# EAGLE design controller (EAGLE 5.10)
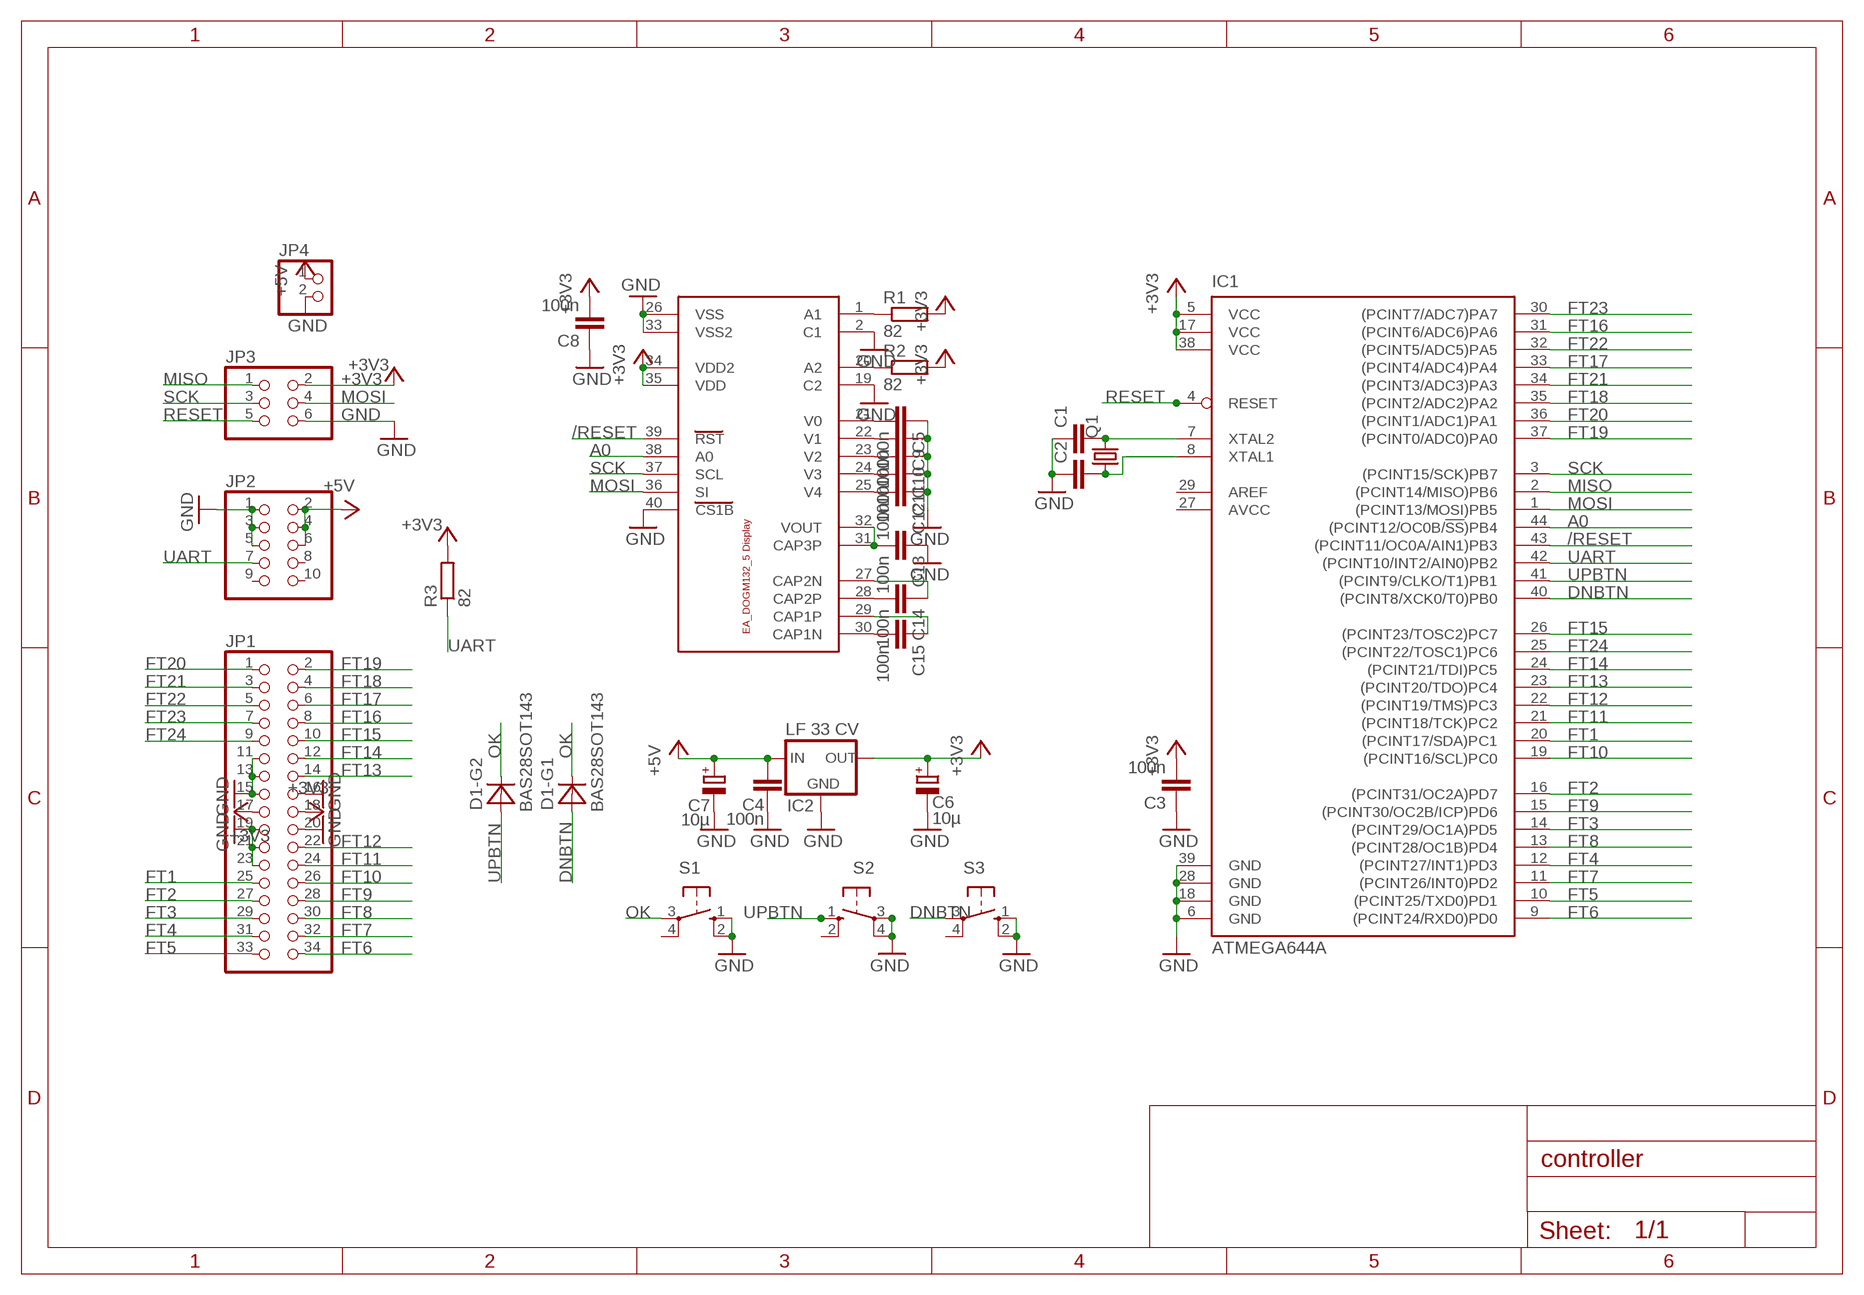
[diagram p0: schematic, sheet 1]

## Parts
C1  C-EUC1206  [C1206]
C2  C-EUC1206  [C1206]
C3  100n  C-EUC1206  [C1206]
C4  100n  C-EUC1206  [C1206]
C5  100n  C-EUC1206  [C1206]
C6  10µ  CPOL-EU153CLV-0505  [153CLV-0505]
C7  10µ  CPOL-EU153CLV-0505  [153CLV-0505]
C8  100n  C-EUC1206  [C1206]
C9  100n  C-EUC1206  [C1206]
C10  100n  C-EUC1206  [C1206]
C11  100n  C-EUC1206  [C1206]
C12  100n  C-EUC1206  [C1206]
C13  100n  C-EUC1206  [C1206]
C14  100n  C-EUC1206  [C1206]
C15  100n  C-EUC1206  [C1206]
D1  BAS28SOT143  [SOT143-R]
IC1  ATMEGA644A  [TQFP44]
IC2  LF 33 CV  78MXXS  [78MXXS]
JP1  PINHD-2X17  [2X17]
JP2  PINHD-2X5  [2X05]
JP3  PINHD-2X3  [2X03]
JP4  PINHD-1X2  [1X02]
Q1  CRYSTALHC49S  [HC49/S]
R1  82  R-EU_R1206  [R1206]
R2  82  R-EU_R1206  [R1206]
R3  82  R-EU_R1206  [R1206]
S1  10-XX  [B3F-10XX]
S2  10-XX  [B3F-10XX]
S3  10-XX  [B3F-10XX]
U$1  EA_DOG-M_DISPLAY  [E_DOG-M_DISPLAY]

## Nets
+3V3: C3.2 C6.+ C8.2 IC1.5(VCC) IC1.17(VCC) IC1.38(VCC) IC2.OUT JP1.17 JP1.18 JP3.2 R1.2 R2.2 R3.2 U$1.34(VDD2) U$1.35(VDD)
+5V: C4.2 C7.+ IC2.IN JP2.2 JP2.4 JP2.6 JP4.1
/RESET: IC1.43((PCINT11/OC0A/AIN1)PB3) U$1.39(RST)
A0: IC1.44((PCINT12/OC0B/!SS!)PB4) U$1.38(A0)
DNBTN: D1.4(-G1:A) IC1.40((PCINT8/XCK0/T0)PB0) S3.3(P)
FT1: IC1.20((PCINT17/SDA)PC1) JP1.25
FT2: IC1.16((PCINT31/OC2A)PD7) JP1.27
FT3: IC1.14((PCINT29/OC1A)PD5) JP1.29
FT4: IC1.12((PCINT27/INT1)PD3) JP1.31
FT5: IC1.10((PCINT25/TXD0)PD1) JP1.33
FT6: IC1.9((PCINT24/RXD0)PD0) JP1.34
FT7: IC1.11((PCINT26/INT0)PD2) JP1.32
FT8: IC1.13((PCINT28/OC1B)PD4) JP1.30
FT9: IC1.15((PCINT30/OC2B/ICP)PD6) JP1.28
FT10: IC1.19((PCINT16/SCL)PC0) JP1.26
FT11: IC1.21((PCINT18/TCK)PC2) JP1.24
FT12: IC1.22((PCINT19/TMS)PC3) JP1.22
FT13: IC1.23((PCINT20/TDO)PC4) JP1.14
FT14: IC1.24((PCINT21/TDI)PC5) JP1.12
FT15: IC1.26((PCINT23/TOSC2)PC7) JP1.10
FT16: IC1.31((PCINT6/ADC6)PA6) JP1.8
FT17: IC1.33((PCINT4/ADC4)PA4) JP1.6
FT18: IC1.35((PCINT2/ADC2)PA2) JP1.4
FT19: IC1.37((PCINT0/ADC0)PA0) JP1.2
FT20: IC1.36((PCINT1/ADC1)PA1) JP1.1
FT21: IC1.34((PCINT3/ADC3)PA3) JP1.3
FT22: IC1.32((PCINT5/ADC5)PA5) JP1.5
FT23: IC1.30((PCINT7/ADC7)PA7) JP1.7
FT24: IC1.25((PCINT22/TOSC1)PC6) JP1.9
GND: C1.1 C2.1 C3.1 C4.1 C5.1 C6.- C7.- C8.1 C9.1 C10.1 C11.1 C12.1 C13.1 IC1.6(GND) IC1.18(GND) IC1.28(GND) IC1.39(GND) IC2.GND JP1.11 JP1.13 JP1.15 JP1.16 JP1.19 JP1.20 JP1.21 JP1.23 JP2.1 JP2.3 JP2.5 JP3.6 JP4.2 S1.1(S) S1.2(S1) S2.3(P) S2.4(P1) S3.1(S) S3.2(S1) U$1.2(C1) U$1.19(C2) U$1.26(VSS) U$1.33(VSS2) U$1.40(CS1B)
MISO: IC1.2((PCINT14/MISO)PB6) JP3.1
MOSI: IC1.1((PCINT13/MOSI)PB5) JP3.4 U$1.36(SI)
N$1: C1.2 IC1.7(XTAL2) Q1.2
N$2: C2.2 IC1.8(XTAL1) Q1.1
N$3: C5.2 U$1.21(V0)
N$4: C9.2 U$1.22(V1)
N$5: C10.2 U$1.23(V2)
N$6: C11.2 U$1.24(V3)
N$7: C12.2 U$1.25(V4)
N$8: C14.2 U$1.28(CAP2P)
N$9: C15.2 U$1.30(CAP1N)
N$10: C13.2 U$1.31(CAP3P) U$1.32(VOUT)
N$11: R1.1 U$1.1(A1)
N$12: R2.1 U$1.20(A2)
N$15: C14.1 U$1.27(CAP2N)
N$16: C15.1 U$1.29(CAP1P)
OK: D1.1(-G1:C) D1.2(-G2:C) S1.3(P)
RESET: IC1.4(RESET) JP3.5
SCK: IC1.3((PCINT15/SCK)PB7) JP3.3 U$1.37(SCL)
UART: IC1.42((PCINT10/INT2/AIN0)PB2) JP2.7 R3.1
UPBTN: D1.3(-G2:A) IC1.41((PCINT9/CLKO/T1)PB1) S2.1(S)
Unconnected: IC1.29(AREF) JP2.8 JP2.9 JP2.10 S1.4(P1) S2.2(S1) S3.4(P1)

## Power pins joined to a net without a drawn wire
AVCC: IC1.27(AVCC)

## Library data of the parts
C1-C5 C8-C15 = rcl:C-EU: CAPACITOR, European symbol
C6 C7 = rcl:CPOL-EU: POLARIZED CAPACITOR, European symbol
D1 = diode:BAS28: The BAS28 consists of two high-speed switching diodes, fabricated in planar technology, and encapsulated in the small plastic SMD SOT143 package. The diodes are not connected.
IC1 = atmel:ATMEGA644: 8-bit Microcontroller with 64K Bytes In-System Programmable Flash Source: http://www.atmel.com/dyn/resources/prod_documents/doc2593.pdf
IC2 = v-reg:78MXXS: VOLTAGE REGULATOR
JP1 = pinhead:PINHD-2X17: PIN HEADER
JP2 = pinhead:PINHD-2X5: PIN HEADER
JP3 = pinhead:PINHD-2X3: PIN HEADER
JP4 = pinhead:PINHD-1X2: PIN HEADER
Q1 = crystal:CRYSTAL: CRYSTAL
R1-R3 = rcl:R-EU_: RESISTOR, European symbol
S1-S3 = switch-omron:10-XX: OMRON SWITCH
U$1 = display_ea_dogm132:EA_DOG-M_DISPLAY

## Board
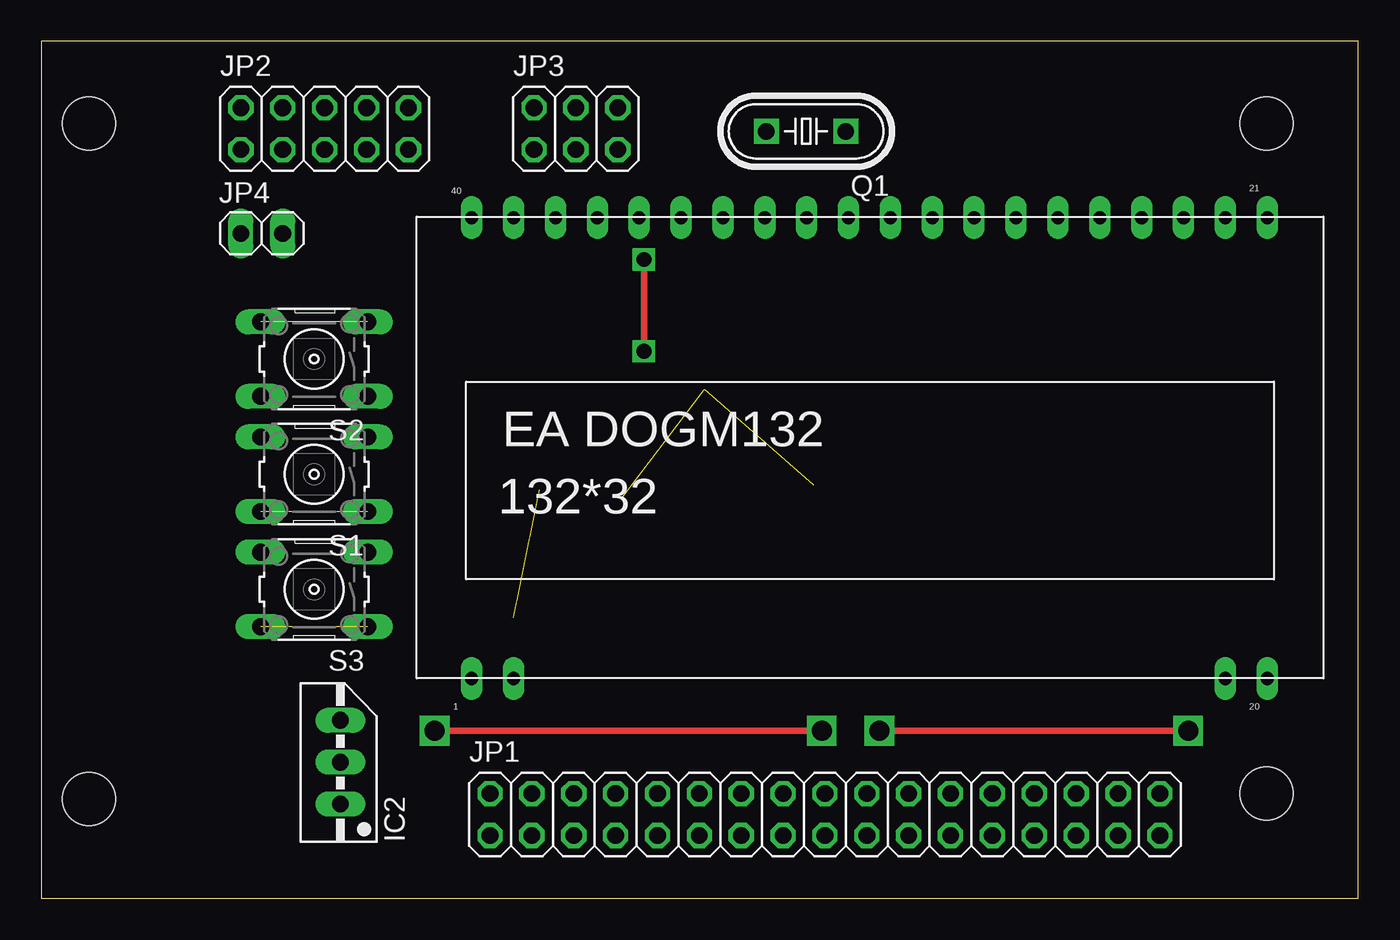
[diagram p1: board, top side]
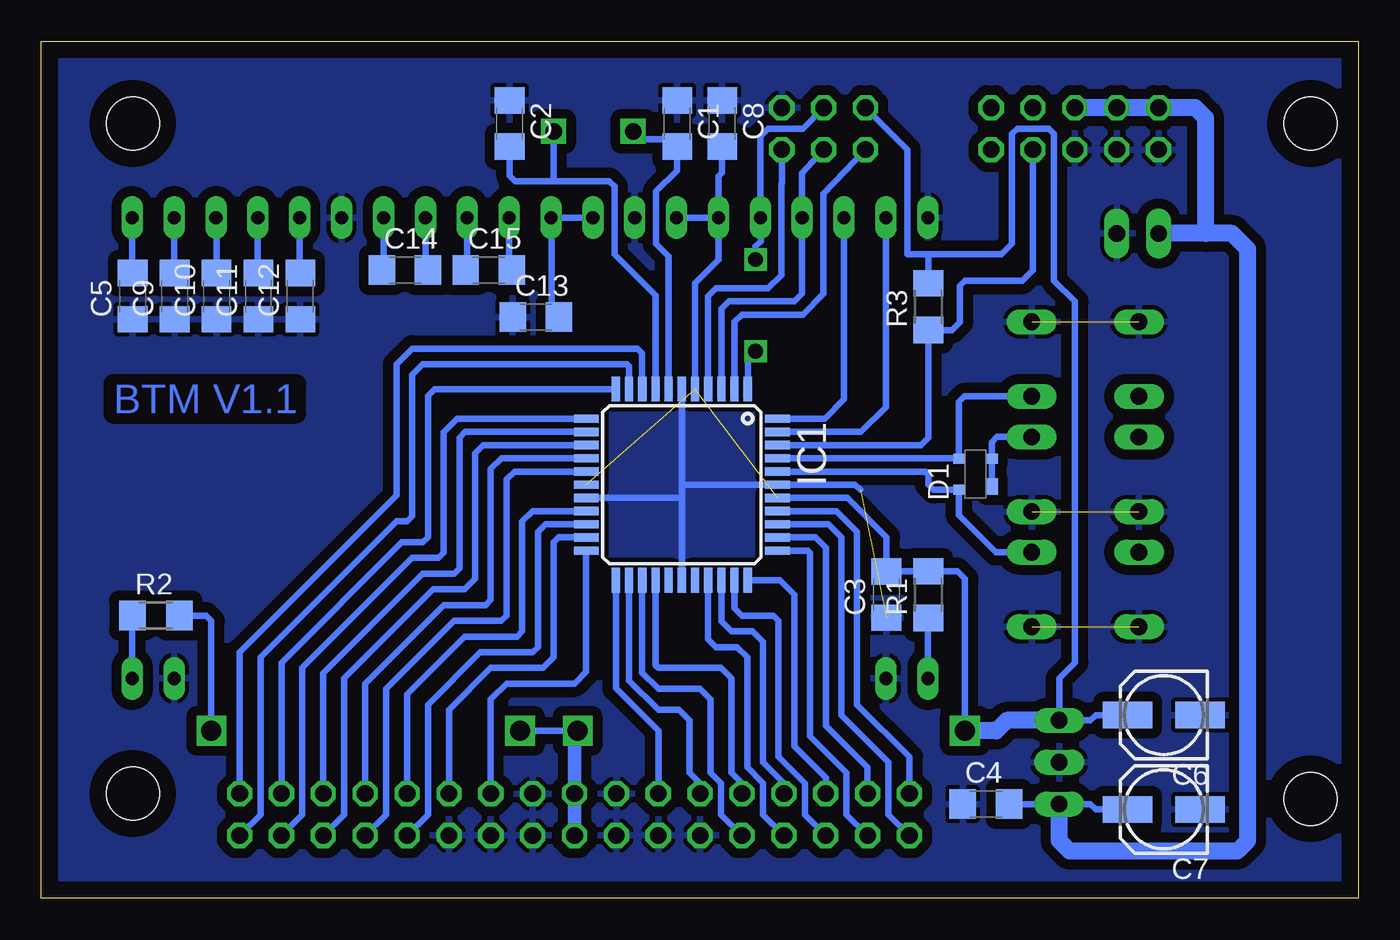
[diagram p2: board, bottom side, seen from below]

Size 79.9 x 51.98 mm. Coordinates in mm from the lower left corner, seen from the top.
Outline: 0,0 79.9,0 79.9,51.98 0,51.98 0,0
Copper layers (1*16): Top 0.035mm / dielectric 1.5mm / Bottom 0.035mm
Design rules "default": minimum track width 10mil, minimum drill 24mil, track to track 8mil, track to pad 8mil, pad to pad 8mil, via to via 8mil, smd to smd 8mil, copper to edge 40mil, drill to drill 8mil, minimum pad ring 10mil, minimum via ring 8mil, stop-mask expansion 4mil, vias tented up to drill 0mil, thermal gap 10mil
Holes 3.2 mm at 74.34,46.99 74.34,6.35 2.9,46.99 2.9,6.03

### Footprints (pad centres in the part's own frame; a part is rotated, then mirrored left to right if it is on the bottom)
C1206 = smd 1.6 x 1.8: 1 -1.4,0; 2 1.4,0
153CLV-0505 = smd 3 x 1.6: + 2.2,0; - -2.2,0
SOT143-R = smd 1 x 0.7: 1 -0.75,-1 | smd 0.6 x 0.7: 2 0.95,-1; 3 0.95,1; 4 -0.95,1
TQFP44 = smd 1.5 x 0.5: 1 -5.8,4; 2 -5.8,3.2; 3 -5.8,2.4; 4 -5.8,1.6; 5 -5.8,0.8; 6 -5.8,0; 7 -5.8,-0.8; 8 -5.8,-1.6; 9 -5.8,-2.4; 10 -5.8,-3.2; 11 -5.8,-4; 23 5.8,-4; 24 5.8,-3.2; 25 5.8,-2.4; 26 5.8,-1.6; 27 5.8,-0.8; 28 5.8,0; 29 5.8,0.8; 30 5.8,1.6; 31 5.8,2.4; 32 5.8,3.2; 33 5.8,4 | smd 0.5 x 1.5: 12 -4,-5.8; 13 -3.2,-5.8; 14 -2.4,-5.8; 15 -1.6,-5.8; 16 -0.8,-5.8; 17 0,-5.8; 18 0.8,-5.8; 19 1.6,-5.8; 20 2.4,-5.8; 21 3.2,-5.8; 22 4,-5.8; 34 4,5.8; 35 3.2,5.8; 36 2.4,5.8; 37 1.6,5.8; 38 0.8,5.8; 39 0,5.8; 40 -0.8,5.8; 41 -1.6,5.8; 42 -2.4,5.8; 43 -3.2,5.8; 44 -4,5.8
78MXXS = drill 1.016 long: GND 0,-2.54; IN -2.54,-2.54; OUT 2.54,-2.54
2X17 = drill 1.016 octagon: 1 -20.32,-1.27; 2 -20.32,1.27; 3 -17.78,-1.27; 4 -17.78,1.27; 5 -15.24,-1.27; 6 -15.24,1.27; 7 -12.7,-1.27; 8 -12.7,1.27; 9 -10.16,-1.27; 10 -10.16,1.27; 11 -7.62,-1.27; 12 -7.62,1.27; 13 -5.08,-1.27; 14 -5.08,1.27; 15 -2.54,-1.27; 16 -2.54,1.27; 17 0,-1.27; 18 0,1.27; 19 2.54,-1.27; 20 2.54,1.27; 21 5.08,-1.27; 22 5.08,1.27; 23 7.62,-1.27; 24 7.62,1.27; 25 10.16,-1.27; 26 10.16,1.27; 27 12.7,-1.27; 28 12.7,1.27; 29 15.24,-1.27; 30 15.24,1.27; 31 17.78,-1.27; 32 17.78,1.27; 33 20.32,-1.27; 34 20.32,1.27
2X05 = drill 1.016 octagon: 1 -5.08,-1.27; 2 -5.08,1.27; 3 -2.54,-1.27; 4 -2.54,1.27; 5 0,-1.27; 6 0,1.27; 7 2.54,-1.27; 8 2.54,1.27; 9 5.08,-1.27; 10 5.08,1.27
2X03 = drill 1.016 octagon: 1 -2.54,-1.27; 2 -2.54,1.27; 3 0,-1.27; 4 0,1.27; 5 2.54,-1.27; 6 2.54,1.27
1X02 = drill 1.016 long: 1 -1.27,0; 2 1.27,0
HC49/S = drill 1 square: 1 -2.413,0; 2 2.413,0
R1206 = smd 1.6 x 1.803: 1 -1.422,0; 2 1.422,0
B3F-10XX = drill 1.016 long: 1 -3.251,2.261; 2 3.251,2.261; 3 -3.251,-2.261; 4 3.251,-2.261
E_DOG-M_DISPLAY = drill 0.8 long: 1 3.334,0; 2 5.874,0; 19 49.054,0; 20 51.594,0; 21 51.594,27.94; 22 49.054,27.94; 23 46.514,27.94; 24 43.974,27.94; 25 41.434,27.94; 26 38.894,27.94; 27 36.354,27.94; 28 33.814,27.94; 29 31.274,27.94; 30 28.734,27.94; 31 26.194,27.94; 32 23.654,27.94; 33 21.114,27.94; 34 18.574,27.94; 35 16.034,27.94; 36 13.494,27.94; 37 10.954,27.94; 38 8.414,27.94; 39 5.874,27.94; 40 3.334,27.94

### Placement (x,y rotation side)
C1  41.32,46.99 270 bottom
C2  51.48,46.99 270 bottom
C3  28.62,18.41 90 bottom
C4  22.59,5.71 0 bottom
C5  74.34,36.51 90 bottom
C6  11.79,11.11 180 bottom
C7  11.79,5.4 180 bottom
C8  38.59,46.99 270 bottom
C9  71.8,36.51 90 bottom
C10  69.26,36.51 90 bottom
C11  66.72,36.51 90 bottom
C12  64.18,36.51 90 bottom
C13  49.89,35.24 0 bottom
C14  57.83,38.1 0 bottom
C15  52.75,38.1 0 bottom
D1  23.22,25.72 90 bottom
IC1  41.04,25.08 270 bottom
IC2  15.6,8.26 90 top
JP1  47.55,5.08 0 top
JP2  17.19,46.67 0 top
JP3  32.43,46.67 0 top
JP4  13.38,40.32 0 top
Q1  46.4,46.51 180 top
R1  26.08,18.41 90 bottom
R2  72.94,17.14 0 bottom
R3  26.08,35.88 90 bottom
S1  16.56,25.72 180 top
S2  16.56,32.7 180 top
S3  16.56,18.73 180 top
U$1  22.78,13.34 0 top

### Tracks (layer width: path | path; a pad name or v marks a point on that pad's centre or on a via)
+3V3  (via drill 1.2)  (2 unrouted)
  Top 0.406: v50.85,10.16 v69.58,10.16 | v23.86,10.16 v47.35,10.16
  Bottom 0.406: IC1.5 40.24,37.31 38.81,38.73 U$1.35 | U$1.35 U$1.34 | U$1.35 38.81,43.78 38.59,44.01 C8.2 | IC1.38 31,24.28 28.62,21.91 C3.2 28.6,19.84 R1.2 24.33,19.84 23.86,19.37 v23.86,10.16 | R2.2 69.9,17.14 69.58,16.83 v69.58,10.16 | v47.35,10.16 v50.85,10.16 | C6.+ 15.92,11.11 16.24,10.79 IC2.OUT 18.15,13.34 17.19,14.29 17.19,36.2 18.46,37.47 18.46,46.35 18.78,46.67 20.68,46.67 21,46.35 21,39.69 21.64,39.05 26.08,39.05 | JP3.2 27.35,45.4 27.35,39.05 26.08,39.05 | 26.08,39.05 R3.2
  Bottom 0.813: JP1.17 JP1.18 47.55,9.97 v47.35,10.16
  Bottom 1.016: v23.86,10.16 21.95,10.16 21.32,10.79 IC2.OUT
+5V
  Bottom 0.406: C4.2 IC2.IN 16.24,5.71 15.92,5.4 C7.+
  Bottom 1.016: JP2.6 JP2.4 JP2.2 9.89,47.94 9.25,47.31 9.25,40.32 | IC2.IN 18.15,3.49 17.51,2.86 7.35,2.86 6.72,3.49 6.72,39.37 7.67,40.32 9.25,40.32 | 9.25,40.32 JP4.1
/RESET
  Bottom 0.406: IC1.43 30.16,28.28 28.65,29.79 U$1.39
A0
  Bottom 0.406: U$1.38 31.19,30.25 32.36,29.08 IC1.44
DNBTN
  Bottom 0.406: IC1.40 26.25,25.88 26.08,25.72 26.08,25.08 25.77,24.77 D1.4 24.22,23.23 21.99,20.99 S3.3
FT1
  Bottom 0.406: IC1.20 49.31,22.68 49.77,22.23 49.77,15.24 50.09,14.92 53.26,14.92 56.44,11.75 56.44,5.08 JP1.25
FT2
  Bottom 0.406: IC1.16 51.19,25.88 51.67,25.4 51.67,17.14 51.99,16.83 54.85,16.83 58.98,12.7 58.98,5.08 JP1.27
FT3
  Bottom 0.406: IC1.14 53.08,27.48 53.58,26.99 53.58,19.37 54.21,18.73 56.12,18.73 61.52,13.34 61.52,5.08 JP1.29
FT4
  Bottom 0.406: IC1.12 54.66,29.08 55.48,28.26 55.48,20.95 55.8,20.64 57.39,20.64 64.05,13.97 64.05,5.08 JP1.31
FT5
  Bottom 0.406: IC1.10 44.24,32.25 44.37,32.38 56.75,32.38 57.39,31.75 57.39,23.18 57.7,22.86 58.34,22.86 66.59,14.61 66.59,5.08 JP1.33
FT6
  Bottom 0.406: IC1.9 43.44,33.04 43.74,33.34 57.39,33.34 58.34,32.38 58.34,24.45 67.86,14.92 JP1.34
FT7
  Bottom 0.406: IC1.11 56.03,30.88 56.44,30.48 56.44,21.91 56.75,21.59 58.02,21.59 65.33,14.29 JP1.32
FT8
  Bottom 0.406: IC1.13 54.19,28.28 54.53,27.94 54.53,20 54.85,19.68 56.75,19.68 62.78,13.65 JP1.30
FT9
  Bottom 0.406: IC1.15 51.98,26.68 52.63,26.04 52.63,18.1 52.94,17.78 55.48,17.78 60.24,13.02 JP1.28
FT10
  Bottom 0.406: IC1.19 50.1,23.48 50.72,22.86 50.72,16.19 51.04,15.88 54.21,15.88 57.7,12.38 JP1.26
FT11
  Bottom 0.406: IC1.21 48.52,21.88 48.81,21.59 48.81,14.61 49.45,13.97 52.63,13.97 55.16,11.43 JP1.24
FT12
  Bottom 0.406: IC1.22 46.84,13.73 47.55,13.02 51.67,13.02 52.63,12.06 JP1.22
FT13
  Bottom 0.406: IC1.23 45.04,12.73 42.46,10.16 JP1.14
FT14
  Bottom 0.406: JP1.12 39.92,6.99 40.56,7.62 40.56,10.79 41.2,11.43 42.46,11.43 44.24,13.2 IC1.24
FT15
  Bottom 0.406: JP1.10 37.38,6.99 38.02,7.62 38.02,13.34 38.66,13.97 42.46,13.97 42.64,14.14 IC1.26
FT16
  Bottom 0.406: JP1.8 34.84,6.99 36.12,8.26 36.12,15.56 36.75,16.19 38.02,16.19 38.64,16.81 IC1.31
FT17
  Bottom 0.406: JP1.6 32.31,7.3 34.21,9.21 34.21,18.41 35.08,19.28 IC1.33
FT18
  Bottom 0.406: JP1.4 29.77,7.94 32.31,10.48 32.31,21.27 32.91,21.88 IC1.35
FT19
  Bottom 0.406: IC1.37 31.66,23.48 30.4,22.23 30.4,11.75 27.22,8.57 JP1.2
FT20
  Bottom 0.406: JP1.1 28.5,5.08 28.5,8.26 31.35,11.11 31.35,21.91 32.13,22.68 IC1.36
FT21
  Bottom 0.406: IC1.34 33.38,21.08 33.26,20.95 33.26,9.84 31.04,7.62 31.04,5.08 JP1.3
FT22
  Bottom 0.406: JP1.5 33.58,5.08 33.58,6.99 35.16,8.57 35.16,16.83 35.48,17.14 37.38,17.14 37.84,17.6 IC1.32
FT23
  Bottom 0.406: JP1.7 36.12,5.08 36.12,6.99 37.07,7.94 37.07,14.61 37.7,15.24 38.97,15.24 39.44,15.7 IC1.30
FT24
  Bottom 0.406: JP1.9 38.66,5.08 38.66,6.99 39.29,7.62 39.29,12.06 39.92,12.7 42.46,12.7 43.44,13.67 IC1.25
GND  (4 unrouted)
  Bottom 0.406: 41.04,24.28 IC1.28 | 41.04,24.28 IC1.18 | 41.04,24.92 41.04,24.28 | 41.04,24.92 IC1.6 | 41.04,24.92 40.88,25.08 IC1.39 30.53,25.08 30.21,24.77
  pour Bottom: 36.99,29.05 36.99,21.11 44.93,21.11 44.93,29.05
  pour Bottom (isolate 0.61): 0,0 79.9,0 79.9,51.98 0,51.98
MISO
  Bottom 0.406: IC1.2 37.84,34.95 37.38,35.4 33.7,35.4 32.43,36.67 32.43,42.73 JP3.1
MOSI  (via drill 0.9)
  Top 0.406: v36.56,33.18 v36.56,38.73
  Bottom 0.406: IC1.1 37.04,32.7 v36.56,33.18 | v36.56,38.73 36.56,39.53 36.24,39.85 36.24,41.24 U$1.36 36.27,46.22 35.81,46.68 33.69,46.68 JP3.4
N$1
  Bottom 0.406: IC1.7 41.84,38.93 42.59,39.69 42.59,42.86 41.32,44.13 C1.2 41.32,46.04 43.86,46.04 43.99,46.16 Q1.2
N$2
  Bottom 0.406: IC1.8 42.64,36.56 45.13,39.05 45.13,43.18 45.45,43.5 48.94,43.5 | 48.94,43.5 51.16,43.5 51.48,43.81 C2.2 | Q1.1 48.82,43.62 48.94,43.5
N$3
  Bottom 0.406: C5.2 74.37,37.94 U$1.21
N$4
  Bottom 0.406: C9.2 71.83,37.94 U$1.22
N$5
  Bottom 0.406: U$1.23 69.26,41.24 C10.2
N$6
  Bottom 0.406: C11.2 66.75,37.94 U$1.24
N$7
  Bottom 0.406: C12.2 64.21,37.94 U$1.25
N$8
  Bottom 0.406: C14.2 56.59,38.26 U$1.28
N$9
  Bottom 0.406: C15.2 51.51,38.26 U$1.30
N$10
  Bottom 0.406: 46.42,41.27 U$1.32 U$1.31 48.94,41.24 48.94,35.69 C13.2
N$11
  Bottom 0.406: U$1.1 26.11,16.96 R1.1
N$12
  Bottom 0.406: R2.1 74.37,15.88 U$1.20
N$15
  Bottom 0.406: C14.1 59.13,38.2 U$1.27
N$16
  Bottom 0.406: C15.1 54.05,38.2 U$1.29
OK
  Bottom 0.406: S1.3 21.92,27.98 22.22,27.67 D1.2 D1.1
RESET
  Bottom 0.406: IC1.4 39.44,36.52 38.97,36.99 35.8,36.99 35,37.78 35,43.34 34.97,43.37 JP3.5
SCK
  Bottom 0.406: IC1.3 38.64,35.74 38.18,36.2 34.21,36.2 33.73,36.67 U$1.37 33.73,43.97 JP3.3
UART
  Bottom 0.406: JP2.7 19.73,38.1 20.37,37.47 23.86,37.47 24.18,37.15 24.18,34.92 24.65,34.46 R3.1 26.08,27.94 26.54,27.48 IC1.42
UPBTN
  Bottom 0.406: S2.1 23.9,30.44 24.22,30.11 D1.3 24.24,26.68 IC1.41

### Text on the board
Bottom: BTM V1.1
